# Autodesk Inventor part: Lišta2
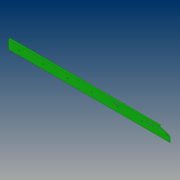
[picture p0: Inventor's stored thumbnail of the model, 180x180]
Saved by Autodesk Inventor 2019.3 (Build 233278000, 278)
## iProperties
Created: 2019-03
Part Number: Lišta2
Material: Ocel, legovaná
Document SubType Name: Plech
Designer: B-hon
Density: 7.73 g/cm^3
Sheet Metal Rule: Výchozí_mm
Appearance: Tmavě zelená
Mass: 1479.03 g
Surface Area: 1973.84 cm^2
Volume: 191.337 cm^3
Author: B-hon
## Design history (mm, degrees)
node "Plocha1"
  sketch "Náčrt1"
    geometry: L1 (0, 0)-(1265.8, 0); L2 (1265.8, 0)-(1265.8, 70); L3 (1265.8, 70)-(0, 70); L4 (0, 70)-(0, 0)
    constraints: 8 end point, 2 parallel, 1 horizontal, 1 perpendicular
    dimensions: "d0" = 1265.8 distance of L3.end L2.end; "d1" = 70 distance of L2.end L1.end
node "Obruba1"
sketch "Náčrt4"
  geometry: L1 (0, 0)-(1265.8, 0) reference; L2 (1265.8, 0)-(1392.184, 0); L3 (1392.184, 0)-(1392.184, 20); L4 (0, 66)-(1265.8, 66) reference; L5 (1265.8, 0)-(1265.8, 66); L6 (1265.8, 66)-(1392.184, 20)
  constraints: 8 end point, 1 horizontal, 1 perpendicular, 1 vertical
  dimensions: "d16" = 20 deg angle of L2 L6; "d19" = 20 distance of L2.end L3.end
extrude "Vysunutí1" join sketch "Náčrt4" distance "d17" = 3; taper "d18" = 0 deg
sketch "Náčrt5"
  geometry: L1 (1412.146, 91.734)-(1245.8, 91.734); L2 (1245.8, 91.734)-(1245.8, -38.323); L3 (1245.8, -38.323)-(1412.146, -38.323); L4 (1412.146, -38.323)-(1412.146, 91.734); L5 (1265.8, 66)-(1265.8, 70) reference; 1 further point
  constraints: 8 end point, 2 parallel, 1 horizontal, 1 perpendicular
  dimensions: "d23" = 20 distance from line of L5.end L2
extrude "Vysunutí2" cut sketch "Náčrt5" distance "d21" = 15; taper "d22" = 0 deg
node "Obruba2"
node "Upravit přímo1"
sketch "Náčrt7"
  geometry: L1 (1255.699, 41.912)-(1165.8, 66); L2 (4, 66)-(1245.8, 66) reference; L3 (1165.8, 66)-(1165.8, 79.178); L4 (1165.8, 79.178)-(1255.699, 79.178); L5 (1255.699, 79.178)-(1255.699, 41.912); L6 (1245.8, 0)-(1245.8, 66) reference; L7 (4, 70)-(1245.8, 70) reference; 1 further point
  constraints: 8 end point, 2 perpendicular, 1 point on line, 1 vertical
  dimensions: "d39" = 80 distance between parallel lines of L6 L3; "d40" = 15 deg angle of L1 L7
extrude "Vysunutí3" cut sketch "Náčrt7" distance "d37" = 15; taper "d38" = 0 deg
fillet "Zaoblení1" dims "d41" = 25
fillet "Zaoblení2" dims "d42" = 6
sketch "Náčrt9"
  geometry: L1 (1245.8, 0)-(1245.8, 25.381) reference; L2 (1245.8, 0)-(4, 0) reference; 2 further points
  dimensions: "d48" = 25.5 distance from line of L1 point (1220.3, 35); "d49" = 35 distance from line of L2 point (1220.3, 35)
hole "Díra1" sketch "Náčrt9" at (1220.3, 35) diameter "d50" = 4.5; stored, may be unused: countersink angle "d54" = 90 deg, drill point angle "d56" = 118 deg; dims "d51" = 6, "d52" = 8.7, "d53" = 2, "d55" = 2 (= Tloušťka)
pattern_linear "Obdélníkové pole1" dims "d59" = 188.9
sketch "Náčrt10"
  geometry: L1 (1245.8, 0)-(4, 0) reference; C1 r 4.35 at (1031.4, 35) reference; 2 further points
  dimensions: "d60" = 188.9 distance of C1.centre point (842.5, 35); "d61" = 35 distance from line of L1 point (842.5, 35)
hole "Díra2" sketch "Náčrt10" at (842.5, 35) diameter "d62" = 4.5; stored, may be unused: countersink angle "d66" = 90 deg, drill point angle "d68" = 118 deg; dims "d63" = 6, "d64" = 8.7, "d65" = 2, "d67" = 2 (= Tloušťka)
sketch "Náčrt11"
  geometry: L1 (811.531, 53)-(850.069, 53); L2 (811.531, 48)-(850.069, 48); L3 (850.069, 58)-(811.531, 58); L4 (1245.8, 0)-(1245.8, 25.381) reference; L5 (4, 70)-(1165.8, 70) reference; A1 r 5 centre (811.531, 53) between (811.531, 58) and (811.531, 48); A2 r 5 centre (850.069, 53) between (850.069, 48) and (850.069, 58); 2 further points
  constraints: 8 end point, 4 point on circle, 4 tangent, 2 centre point, 1 horizontal, 1 midpoint, 1 parallel
  dimensions: "d72" = 10 diameter of A2; "d73" = 415 distance from line of L4 point (830.8, 53); "d74" = 17 distance from line of L5 point (830.8, 53)
extrude "Vysunutí5" cut sketch "Náčrt11" distance "d75" = 10; taper "d76" = 0 deg
pattern_linear "Obdélníkové pole3" dims "d79" = 260
sketch "Náčrt12"
  geometry: L1 (1245.8, 0)-(4, 0) reference; C1 r 4.35 at (842.5, 35) reference; 2 further points
  dimensions: "d80" = 200 distance of C1.centre point (642.5, 35); "d81" = 35 distance from line of L1 point (642.5, 35)
hole "Díra3" sketch "Náčrt12" at (642.5, 35) diameter "d82" = 4.5; stored, may be unused: countersink angle "d86" = 90 deg, drill point angle "d88" = 118 deg; dims "d83" = 6, "d84" = 8.7, "d85" = 2, "d87" = 2 (= Tloušťka)
pattern_linear "Obdélníkové pole4" dims "d91" = 185
node "Těleso1"
feature "Deska1" dims "d2" = 2 (= Tloušťka)
sketch "Náčrt2"
  geometry: L1 through (632.9, 0) direction (-1, 0); L2 through (0, -6) direction (0, -1); L3 (0, -12)-(1265.8, -12); L4 (1265.8, -12)-(1265.8, 0)
  constraints: 6 end point, 1 horizontal, 1 perpendicular, 1 vertical
feature "Deska2" dims "d2" = 2 (= Tloušťka), "d3" = 2 (= ŠířkaVýštipu), "d4" = 1 (= HloubkaVýštipu), "d5" = 4 (= MinimálníZbytek), "d6" = 2 (= PřechodovýPoloměr), "d7" = 12, "d8" = 90 deg, "d9" = 2 (= PoloměrOhybu), "d10" = 8 (= VelikostRohovéhoVýštipu), "d11" = 2 (= VelikostMezery), "d12" = 2 (= VelikostJacobihoPoloměru), "MezeraVystřižení" = 0.01
feature "Ohyb1" dims "d2" = 2 (= Tloušťka), "d3" = 2 (= ŠířkaVýštipu), "d4" = 1 (= HloubkaVýštipu), "d5" = 4 (= MinimálníZbytek), "d6" = 2 (= PřechodovýPoloměr), "d7" = 12, "d8" = 90 deg, "d9" = 2 (= PoloměrOhybu), "MezeraVystřižení" = 0.01
feature "Roh1" dims "d7" = 12, "d8" = 90 deg, "d10" = 8 (= VelikostRohovéhoVýštipu), "d11" = 2 (= VelikostMezery), "d12" = 2 (= VelikostJacobihoPoloměru)
sketch "Náčrt6"
  geometry: L1 through (33, 0) direction (-1, 0); L2 through (0, -7.5) direction (0, -1); L3 (0, -15)-(66, -15); L4 (66, -15)-(66, 0)
  constraints: 6 end point, 1 horizontal, 1 perpendicular, 1 vertical
feature "Deska3" dims "d2" = 2 (= Tloušťka), "d24" = 2 (= ŠířkaVýštipu), "d25" = 1 (= HloubkaVýštipu), "d26" = 4 (= MinimálníZbytek), "d27" = 2 (= PřechodovýPoloměr), "d28" = 15, "d29" = 90 deg, "d30" = 2 (= PoloměrOhybu), "d31" = 8 (= VelikostRohovéhoVýštipu), "d32" = 2 (= VelikostMezery), "d33" = 2 (= VelikostJacobihoPoloměru), "MezeraVystřižení" = 0.01
feature "Ohyb2" dims "d2" = 2 (= Tloušťka), "d24" = 2 (= ŠířkaVýštipu), "d25" = 1 (= HloubkaVýštipu), "d26" = 4 (= MinimálníZbytek), "d27" = 2 (= PřechodovýPoloměr), "d28" = 15, "d29" = 90 deg, "d30" = 2 (= PoloměrOhybu), "MezeraVystřižení" = 0.01
feature "Roh2" dims "d28" = 15, "d29" = 90 deg, "d31" = 8 (= VelikostRohovéhoVýštipu), "d32" = 2 (= VelikostMezery), "d33" = 2 (= VelikostJacobihoPoloměru)
feature "Posunout1" dims "d36" = 0
other parameters: "Tloušťka" = 2, "KSoučinitel" = 4.4, "PoloměrOhybu" = 2 (= Tloušťka), "ŠířkaVýštipu" = 2 (= Tloušťka), "HloubkaVýštipu" = 1 (= 0.5 x Tloušťka), "VelikostRohovéhoVýštipu" = 8 (= 4 x Tloušťka), "MinimálníZbytek" = 4 (= 2 x Tloušťka), "PřechodovýPoloměr" = 2 (= PoloměrOhybu), "VelikostJacobihoPoloměru" = 2 (= PoloměrOhybu), "VelikostMezery" = 2 (= Tloušťka), "d34" = 0, "d35" = 0
